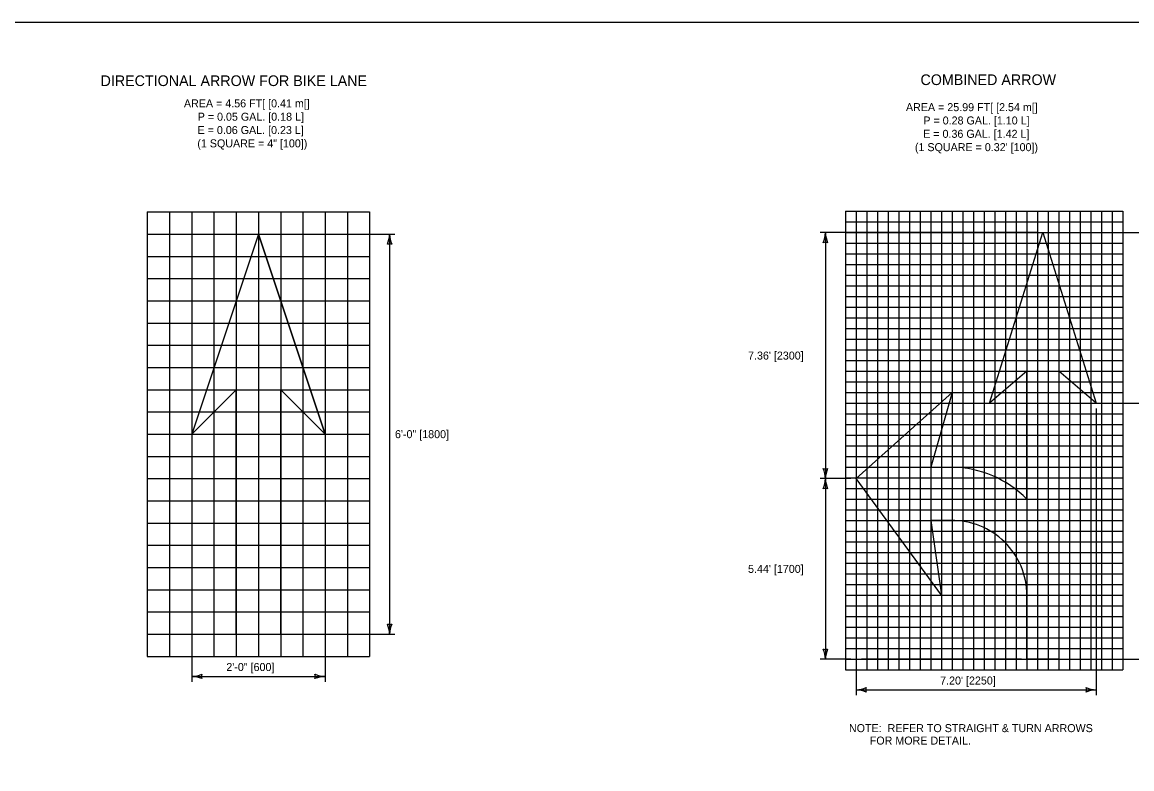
# Model space of a CAD drawing. Extents: x 49991.4 to 50021, y 49980.9 to 50011.4.
# Drawn here: x 50000.07 to 50008.39, y 49993.4 to 49999 of the extents above; entities that cross this region are included whole.
import ezdxf

# ---------------------------------------------------------------- set-up
doc = ezdxf.new("R2010")
doc.units = 0
for name, color, linetype in [('Level 1', 7, 'Continuous'), ('Level 2', 7, 'Continuous'), ('Level 3', 7, 'Continuous'), ('Level 9', 7, 'Continuous')]:
    doc.layers.add(name, color=color, linetype=linetype)

msp = doc.modelspace()

# ---------------------------------------------------------------- linework, layer by layer
at = {"layer": 'Level 1'}
for p, q in [((50001.8443, 49997.4091), (50001.3443, 49995.9091)), ((50001.8443, 49997.4091), (50001.3443, 49995.9091)), ((50002.3443, 49995.9091), (50001.8443, 49997.4091)), ((50001.8443, 49997.4091), (50002.3443, 49995.9091)), ((50007.3237, 49996.1414), (50007.7237, 49997.4214)), ((50007.7237, 49997.4214), (50008.1237, 49996.1414)), ((50007.6037, 49996.3814), (50007.3237, 49996.1414)), ((50007.6037, 49995.4214), (50007.6037, 49996.3814)), ((50008.1237, 49996.1414), (50007.8437, 49996.3814)), ((50007.8437, 49996.3814), (50007.8437, 49994.2214)), ((50001.3443, 49995.9091), (50001.6776, 49996.2425)), ((50001.3443, 49995.9091), (50001.6776, 49996.2425)), ((50001.6776, 49996.2425), (50001.6776, 49994.4091)), ((50001.6776, 49994.4091), (50001.6776, 49996.2425)), ((50002.011, 49994.4091), (50002.011, 49996.2425)), ((50002.011, 49996.2425), (50002.3443, 49995.9091)), ((50002.3443, 49995.9091), (50002.011, 49996.2425)), ((50002.011, 49994.4091), (50002.011, 49996.2425)), ((50006.3237, 49995.5755), (50007.0437, 49996.2214)), ((50007.0437, 49996.2214), (50006.8837, 49995.6614)), ((50006.8837, 49995.6614), (50007.0437, 49995.6614)), ((50006.9637, 49994.7014), (50006.3237, 49995.5755)), ((50007.0347, 49995.2614), (50006.8837, 49995.2614)), ((50006.8837, 49995.2614), (50006.9637, 49994.7014)), ((50007.6037, 49994.2214), (50007.6037, 49994.7014)), ((50001.6776, 49994.4091), (50002.011, 49994.4091)), ((50001.6776, 49994.4091), (50002.011, 49994.4091)), ((50007.8437, 49994.2214), (50007.6037, 49994.2214))]:
    msp.add_line(p, q, dxfattribs=at)
msp.add_lwpolyline([(49999.3835, 49998.9992), (50016.7501, 49998.9992), (50016.7501, 49987.7988), (49999.3835, 49987.7988)], close=True, dxfattribs=at)
for centre, radius, start, end in [((50007.0323, 49994.8615), 0.8, 44.41887, 89.18395), ((50007.0437, 49994.7015), 0.56, 359.99258, 90.92192)]:
    msp.add_arc(centre, radius, start, end, dxfattribs=at)
at = {"layer": 'Level 3'}
for p, q in [((50001.8843, 49997.4091), (50002.8676, 49997.4091)), ((50002.8276, 49997.4091), (50002.8276, 49994.4091)), ((50007.6837, 49997.4214), (50006.0537, 49997.4214)), ((50006.0937, 49997.4214), (50006.0937, 49995.5755)), ((50007.7637, 49997.4214), (50009.0585, 49997.4214)), ((50008.1237, 49996.1014), (50008.1237, 49993.9514)), ((50008.1637, 49996.1414), (50008.5137, 49996.1414)), ((50001.3443, 49995.8691), (50001.3443, 49994.0525)), ((50002.3443, 49995.8691), (50002.3443, 49994.0525)), ((50006.2837, 49995.5755), (50006.0537, 49995.5755)), ((50006.0937, 49995.5755), (50006.0937, 49994.2214)), ((50006.3237, 49995.5355), (50006.3237, 49993.9514)), ((50002.051, 49994.4091), (50002.3043, 49994.4091)), ((50002.3843, 49994.4091), (50002.8676, 49994.4091)), ((50006.2837, 49994.2214), (50006.0537, 49994.2214)), ((50007.5637, 49994.2214), (50006.3637, 49994.2214)), ((50007.8837, 49994.2214), (50008.0837, 49994.2214)), ((50008.1637, 49994.2214), (50009.0585, 49994.2214)), ((50001.3443, 49994.0925), (50002.3443, 49994.0925)), ((50006.3237, 49993.9914), (50008.1237, 49993.9914))]:
    msp.add_line(p, q, dxfattribs=at)
for centre, radius, start, end in [((50002.6055, 49997.4183), 0.2223, 337.45601, 357.63952), ((50003.0603, 49997.4206), 0.233, 182.82731, 202.07716), ((50005.8715, 49997.4305), 0.2223, 337.45601, 357.63952), ((50006.3264, 49997.4329), 0.233, 182.82731, 202.07716), ((50002.8276, 49997.2809), 0.0548, 72.13882, 107.86118), ((50006.0937, 49997.2932), 0.0548, 72.13882, 107.86118), ((50006.0937, 49995.7037), 0.0548, 252.13882, 287.86118), ((50005.8609, 49995.564), 0.233, 2.82731, 22.07716), ((50006.3158, 49995.5664), 0.2223, 157.45601, 177.63952), ((50005.8715, 49995.5847), 0.2223, 337.45601, 357.63952), ((50006.3264, 49995.587), 0.233, 182.82731, 202.07716), ((50006.0937, 49995.4473), 0.0548, 72.13882, 107.86118), ((50002.8276, 49994.5373), 0.0548, 252.13882, 287.86118), ((50002.5949, 49994.3976), 0.233, 2.82731, 22.07716), ((50003.0498, 49994.4), 0.2223, 157.45601, 177.63952), ((50006.0937, 49994.3496), 0.0548, 252.13882, 287.86118), ((50005.8609, 49994.2099), 0.233, 2.82731, 22.07716), ((50006.3158, 49994.2122), 0.2223, 157.45601, 177.63952), ((50001.3328, 49994.3252), 0.233, 272.82731, 292.07716), ((50001.3351, 49993.8703), 0.2223, 67.45601, 87.63952), ((50001.4725, 49994.0925), 0.0548, 162.13882, 197.86118), ((50002.3535, 49994.3146), 0.2223, 247.45601, 267.63952), ((50002.2161, 49994.0925), 0.0548, 342.13882, 17.86118), ((50002.3558, 49993.8597), 0.233, 92.82731, 112.07716), ((50006.3122, 49994.2241), 0.233, 272.82731, 292.07716), ((50006.3145, 49993.7693), 0.2223, 67.45601, 87.63952), ((50006.4519, 49993.9914), 0.0548, 162.13882, 197.86118), ((50008.1328, 49994.2135), 0.2223, 247.45601, 267.63952), ((50007.9954, 49993.9914), 0.0548, 342.13882, 17.86118), ((50008.1352, 49993.7587), 0.233, 92.82731, 112.07716)]:
    msp.add_arc(centre, radius, start, end, dxfattribs=at)
at = {"layer": 'Level 9'}
for p, q in [((50001.011, 49997.5758), (50001.011, 49994.2425)), ((50001.011, 49997.5758), (50002.6776, 49997.5758)), ((50001.1776, 49997.5758), (50001.1776, 49994.2425)), ((50001.3443, 49997.5758), (50001.3443, 49994.2425)), ((50001.511, 49997.5758), (50001.511, 49994.2425)), ((50001.6776, 49997.5758), (50001.6776, 49994.2425)), ((50001.8443, 49997.5758), (50001.8443, 49994.2425)), ((50002.011, 49997.5758), (50002.011, 49994.2425)), ((50002.1776, 49997.5758), (50002.1776, 49994.2425)), ((50002.3443, 49997.5758), (50002.3443, 49994.2425)), ((50002.511, 49997.5758), (50002.511, 49994.2425)), ((50002.6776, 49997.5758), (50002.6776, 49994.2425)), ((50006.2437, 49997.5814), (50006.2437, 49994.1414)), ((50006.2437, 49997.5814), (50008.3237, 49997.5814)), ((50006.3237, 49997.5814), (50006.3237, 49994.1414)), ((50006.4037, 49997.5814), (50006.4037, 49994.1414)), ((50006.4837, 49997.5814), (50006.4837, 49994.1414)), ((50006.5637, 49997.5814), (50006.5637, 49994.1414)), ((50006.6437, 49997.5814), (50006.6437, 49994.1414)), ((50006.7237, 49997.5814), (50006.7237, 49994.1414)), ((50006.8037, 49997.5814), (50006.8037, 49994.1414)), ((50006.8837, 49997.5814), (50006.8837, 49994.1414)), ((50006.9637, 49997.5814), (50006.9637, 49994.1414)), ((50007.0437, 49997.5814), (50007.0437, 49994.1414)), ((50007.1237, 49997.5814), (50007.1237, 49994.1414)), ((50007.2037, 49997.5814), (50007.2037, 49994.1414)), ((50007.2837, 49997.5814), (50007.2837, 49994.1414)), ((50007.3637, 49997.5814), (50007.3637, 49994.1414)), ((50007.4437, 49997.5814), (50007.4437, 49994.1414)), ((50007.5237, 49997.5814), (50007.5237, 49994.1414)), ((50007.6037, 49997.5814), (50007.6037, 49994.1414)), ((50007.6837, 49997.5814), (50007.6837, 49994.1414)), ((50007.7637, 49997.5814), (50007.7637, 49994.1414)), ((50007.8437, 49997.5814), (50007.8437, 49994.1414)), ((50007.9237, 49997.5814), (50007.9237, 49994.1414)), ((50008.0037, 49997.5814), (50008.0037, 49994.1414)), ((50008.0837, 49997.5814), (50008.0837, 49994.1414)), ((50008.1637, 49997.5814), (50008.1637, 49994.1414)), ((50008.2437, 49997.5814), (50008.2437, 49994.1414)), ((50008.3237, 49997.5814), (50008.3237, 49994.1414)), ((50006.2437, 49997.5014), (50008.3237, 49997.5014)), ((50001.011, 49997.4091), (50002.6776, 49997.4091)), ((50006.2437, 49997.4214), (50008.3237, 49997.4214)), ((50006.2437, 49997.3414), (50008.3237, 49997.3414)), ((50001.011, 49997.2424), (50002.6776, 49997.2424)), ((50006.2437, 49997.2614), (50008.3237, 49997.2614)), ((50006.2437, 49997.1814), (50008.3237, 49997.1814)), ((50001.011, 49997.0758), (50002.6776, 49997.0758)), ((50006.2437, 49997.1014), (50008.3237, 49997.1014)), ((50006.2437, 49997.0214), (50008.3237, 49997.0214)), ((50001.011, 49996.9091), (50002.6776, 49996.9091)), ((50006.2437, 49996.9414), (50008.3237, 49996.9414)), ((50006.2437, 49996.8614), (50008.3237, 49996.8614)), ((50001.011, 49996.7425), (50002.6776, 49996.7425)), ((50006.2437, 49996.7814), (50008.3237, 49996.7814)), ((50006.2437, 49996.7014), (50008.3237, 49996.7014)), ((50001.011, 49996.5758), (50002.6776, 49996.5758)), ((50006.2437, 49996.6214), (50008.3237, 49996.6214)), ((50006.2437, 49996.5414), (50008.3237, 49996.5414)), ((50001.011, 49996.4091), (50002.6776, 49996.4091)), ((50006.2437, 49996.4614), (50008.3237, 49996.4614)), ((50006.2437, 49996.3814), (50008.3237, 49996.3814)), ((50001.011, 49996.2425), (50002.6776, 49996.2425)), ((50006.2437, 49996.3014), (50008.3237, 49996.3014)), ((50006.2437, 49996.2214), (50008.3237, 49996.2214)), ((50001.011, 49996.0758), (50002.6776, 49996.0758)), ((50006.2437, 49996.1414), (50008.3237, 49996.1414)), ((50006.2437, 49996.0614), (50008.3237, 49996.0614)), ((50006.2437, 49995.9814), (50008.3237, 49995.9814)), ((50001.011, 49995.9091), (50002.6776, 49995.9091)), ((50006.2437, 49995.9014), (50008.3237, 49995.9014)), ((50006.2437, 49995.8214), (50008.3237, 49995.8214)), ((50001.011, 49995.7425), (50002.6776, 49995.7425)), ((50006.2437, 49995.7414), (50008.3237, 49995.7414)), ((50006.2437, 49995.6614), (50008.3237, 49995.6614)), ((50001.011, 49995.5758), (50002.6776, 49995.5758)), ((50006.2437, 49995.5814), (50008.3237, 49995.5814)), ((50006.2437, 49995.5014), (50008.3237, 49995.5014)), ((50001.011, 49995.4091), (50002.6776, 49995.4091)), ((50006.2437, 49995.4214), (50008.3237, 49995.4214)), ((50006.2437, 49995.3414), (50008.3237, 49995.3414)), ((50001.011, 49995.2425), (50002.6776, 49995.2425)), ((50006.2437, 49995.2614), (50008.3237, 49995.2614)), ((50006.2437, 49995.1814), (50008.3237, 49995.1814)), ((50001.011, 49995.0758), (50002.6776, 49995.0758)), ((50006.2437, 49995.1014), (50008.3237, 49995.1014)), ((50006.2437, 49995.0214), (50008.3237, 49995.0214)), ((50001.011, 49994.9091), (50002.6776, 49994.9091)), ((50006.2437, 49994.9414), (50008.3237, 49994.9414)), ((50006.2437, 49994.8614), (50008.3237, 49994.8614)), ((50001.011, 49994.7425), (50002.6776, 49994.7425)), ((50006.2437, 49994.7814), (50008.3237, 49994.7814)), ((50006.2437, 49994.7014), (50008.3237, 49994.7014)), ((50001.011, 49994.5758), (50002.6776, 49994.5758)), ((50006.2437, 49994.6214), (50008.3237, 49994.6214)), ((50006.2437, 49994.5414), (50008.3237, 49994.5414)), ((50001.011, 49994.4091), (50002.6776, 49994.4091)), ((50006.2437, 49994.4614), (50008.3237, 49994.4614)), ((50006.2437, 49994.3814), (50008.3237, 49994.3814)), ((50001.011, 49994.2425), (50002.6776, 49994.2425)), ((50006.2437, 49994.3014), (50008.3237, 49994.3014)), ((50006.2437, 49994.2214), (50008.3237, 49994.2214)), ((50006.2437, 49994.1414), (50008.3237, 49994.1414))]:
    msp.add_line(p, q, dxfattribs=at)

# ---------------------------------------------------------------- texts
at = {"layer": 'Level 2'}
for s, height, p in [('DIRECTIONAL ARROW FOR BIKE LANE', 0.08, (50000.6611, 49998.5201)), ('COMBINED ARROW', 0.08, (50006.8064, 49998.5276)), ('AREA = 4.56 FT[ [0.41 m[]', 0.06, (50001.2858, 49998.3601)), ('AREA = 25.99 FT[ [2.54 m[]', 0.06, (50006.6975, 49998.3318)), ('P = 0.05 GAL. [0.18 L]', 0.06, (50001.3892, 49998.2601)), ('P = 0.28 GAL. [1.10 L]', 0.06, (50006.8279, 49998.2318)), ('E = 0.06 GAL. [0.23 L]', 0.06, (50001.3881, 49998.1601)), ('E = 0.36 GAL. [1.42 L]', 0.06, (50006.8267, 49998.1318)), ('(1 SQUARE = 4" [100])', 0.06, (50001.3864, 49998.0601)), ("(1 SQUARE = 0.32' [100])", 0.06, (50006.7646, 49998.0318)), ("7.36' [2300]", 0.06, (50005.514, 49996.4685)), ('6\'-0" [1800]', 0.06, (50002.8676, 49995.8791)), ("5.44' [1700]", 0.06, (50005.514, 49994.8685)), ('2\'-0" [600]', 0.06, (50001.6035, 49994.1325)), ("7.20' [2250]", 0.06, (50006.9538, 49994.0314)), ('NOTE:  REFER TO STRAIGHT & TURN ARROWS', 0.06, (50006.2703, 49993.6742)), ('       FOR MORE DETAIL.', 0.06, (50006.2703, 49993.5808))]:
    msp.add_text(s, height=height, dxfattribs=at).set_placement(p)

doc.saveas('drawing.dxf')
